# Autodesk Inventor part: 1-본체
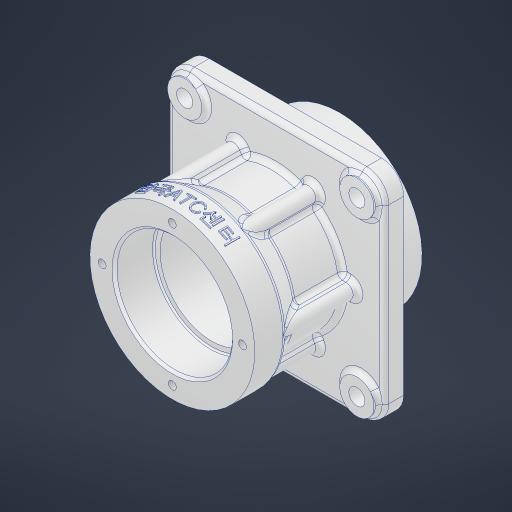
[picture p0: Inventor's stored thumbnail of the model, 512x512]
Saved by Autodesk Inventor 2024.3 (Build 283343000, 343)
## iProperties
Created: 2025-08
Part Number: 1-본체
Material: 알루미늄 6061
Document SubType Name: Modeling
Designer: user
Density: 2.7 g/cm^3
Appearance: 알루미늄 - 평지
Mass: 400.714 g
Surface Area: 396.891 cm^2
Volume: 148.413 cm^3
Author: user
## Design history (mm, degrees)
sketch "스케치1"
  geometry: L1 (0, 0)-(68, 0); L2 (0, 33.5)-(12, 33.5); L3 (12, 33.5)-(22, 27.5); L4 (0, 33.5)-(0, 0); L5 (22, 27.5)-(55, 27.5); L6 (55, 33.5)-(68, 33.5); L7 (68, 33.5)-(68, 0); L8 (55, 33.5)-(55, 27.5)
  constraints: 16 end point, 3 horizontal, 2 vertical, 1 parallel, 1 perpendicular
  dimensions: "d0" = 68 distance of L1.start L1.end; "d1" = 67 diameter of L2 L1; "d2" = 12 distance of L2.start L2.end; "d4" = 55 diameter of L5 L1; "d5" = 67 diameter of L6 L1; "d6" = 22 horizontal distance of L3.end L2.start; "d7" = 13 distance of L6.start L6.end
revolve "회전1" sketch "스케치1" stored, may be unused: angle "d8" = 90 deg
sketch "스케치2"
  geometry: C1 r 27.5 at (0, 0) reference; C2 r 33.5 at (0, 0) reference; C3 r 38.5 at (0, 0)
  constraints: 1 centre point, 1 coincident
  dimensions: "d9" = 77 diameter of C3
extrude "돌출1" join sketch "스케치2" distance "d10" = 5; taper "d11" = 0 deg
sketch "스케치3"
  geometry: L1 (-44, 44)-(44, 44); L2 (44, 44)-(44, -44); L3 (44, -44)-(-44, -44); L4 (-44, -44)-(-44, 44); C1 r 38.5 at (0, 0) reference; C2 r 27.5 at (0, 0) reference; 2 further points
  constraints: 8 end point, 2 midpoint, 2 parallel, 1 horizontal, 1 horizontal alignment, 1 perpendicular, 1 vertical alignment
  dimensions: "d12" = 88 distance of L2.end L3.end; "d13" = 88 distance of L1.end L2.end
extrude "돌출2" join sketch "스케치3" distance "d14" = 8; taper "d15" = 0 deg
fillet "모깎기1" dims "d16" = 9
sketch "스케치4"
  geometry: C1 r 7 at (-35, 35); C2 r 7 at (35, 35); C3 r 7 at (35, -35); C4 r 7 at (-35, -35); A1 r 9 centre (-35, -35) between (-44, -35) and (-35, -44) reference; A2 r 9 centre (35, -35) between (35, -44) and (44, -35) reference; A3 r 9 centre (35, 35) between (44, 35) and (35, 44) reference; A4 r 9 centre (-35, 35) between (-35, 44) and (-44, 35) reference
  constraints: 4 centre point, 4 coincident
  dimensions: "d17" = 14 diameter of C1; "d18" = 14 diameter of C2; "d19" = 14 diameter of C3; "d20" = 14 diameter of C4
extrude "돌출3" join sketch "스케치4" distance "d21" = 2; taper "d22" = 0 deg
fillet "모깎기2" dims "d23" = 2
sketch "스케치5"
  geometry: A1 r 7 centre (35, 35) between (40.444, 30.6) and (30.6, 40.444) reference; A2 r 7 centre (-35, 35) between (-40.444, 30.6) and (-30.6, 40.444) reference; A3 r 7 centre (35, -35) between (30.6, -40.444) and (40.444, -30.6) reference; A4 r 7 centre (-35, -35) between (-30.6, -40.444) and (-40.444, -30.6) reference; 5 further points
  constraints: 4 coincident
hole "구멍1" sketch "스케치5" at (35, 35), (-35, 35), (35, -35), (-35, -35) diameter "d24" = 6.6; stored, may be unused: countersink angle "d28" = 90 deg, drill point angle "d30" = 118 deg; dims "d25" = 6, "d26" = 4, "d27" = 2, "d29" = 8
fillet "모깎기6" dims "d78" = 2
sketch "스케치6"
  geometry: L1 (0, 0)-(33.5, 0); L2 (30.5, 3)-(27.336, 3); L3 (30.5, -3)-(27.336, -3); A1 r 27.5 centre (0, 0) between (27.336, 3) and (27.336, -3) reference; A2 r 3 centre (30.5, 0) between (27.5, 0) and (30.5, -3); A3 r 3 centre (30.5, 0) between (30.5, 3) and (27.5, 0); A4 r 3 centre (30.5, 0) between (30.5, -3) and (30.5, 3)
  constraints: 11 point on circle, 6 end point, 4 tangent, 3 centre point, 2 horizontal, 1 horizontal alignment, 1 parallel, 1 point on line, 1 other
  dimensions: "d31" = 6 diameter of A2
extrude "돌출4" join sketch "스케치6" stored distance "d32" = 2; taper "d33" = 0 deg
sketch "스케치7"
  geometry: C1 r 33.5 at (0, 0) reference; C2 r 23.5 at (0, 0)
  constraints: 1 centre point, 1 coincident
  dimensions: "d37" = 47 diameter of C2
extrude "돌출5" cut sketch "스케치7" distance "d38" = 16; taper "d39" = 0 deg
sketch "스케치8"
  geometry: C1 r 23.5 at (0, 0) reference; C2 r 21 at (0, 0)
  constraints: 1 centre point, 1 coincident
  dimensions: "d40" = 42 diameter of C2
extrude "돌출6" cut sketch "스케치8" extent not by distance; stored distance "d41" = 0; taper "d42" = 0 deg
sketch "스케치9"
  geometry: C1 r 21 at (0, 0) reference; C2 r 33.5 at (0, 0) reference; C3 r 23.5 at (0, 0)
  constraints: 1 centre point, 1 coincident
  dimensions: "d43" = 47 diameter of C3
extrude "돌출7" cut sketch "스케치9" distance "d44" = 16; taper "d45" = 0 deg
chamfer "모따기1" distance "d46" = 1; stored, may be unused: second distance "d47" = 2, angle "d48" = 45 deg
fillet "모깎기3" dims "d49" = 0.6
sketch "스케치10"
  geometry: L1 (0, 0)-(0, 28.5); C1 r 24.5 at (0, 0) reference; 1 further point
  constraints: 2 end point, 1 coincident, 1 vertical
  dimensions: "d51" = 28.5 distance of L1.start L1.end
hole "구멍2" sketch "스케치10" at (0, 28.5) diameter "d52" = 3.242; stored, may be unused: countersink angle "d56" = 90 deg, drill point angle "d58" = 118 deg; dims "d53" = 8, "d54" = 4, "d55" = 2, "d57" = 10
sketch "스케치11"
  geometry: L1 (0, 0)-(0, 28.5); C1 r 24.5 at (0, 0) reference; 1 further point
  constraints: 2 end point, 1 coincident, 1 vertical
  dimensions: "d62" = 28.5 distance of L1.start L1.end
hole "구멍3" sketch "스케치11" at (0, 28.5) diameter "d63" = 3.242; stored, may be unused: countersink angle "d67" = 90 deg, drill point angle "d69" = 118 deg; dims "d64" = 8, "d65" = 4, "d66" = 2, "d68" = 10
chamfer "모따기2" distance "d73" = 1; stored, may be unused: second distance "d74" = 2, angle "d75" = 45 deg
fillet "모깎기5" dims "d77" = 2
fillet "모깎기7" dims "d79" = 2
fillet "모깎기8" dims "d80" = 2
fillet "모깎기9" dims "d81" = 2
node "작업 평면1"
sketch "스케치12" dims "d0" = 68, "d1" = 67, "d2" = 12, "d4" = 55, "d5" = 67, "d6" = 22, "d7" = 13
  geometry: L1 (6, 33.5)-(-5.446, 33.5) reference; L2 (6, 33.5)-(6, -33.5) reference; L3 (-5.446, 33.5)-(-5.446, 16.75) reference; L4 (-5.446, 16.75)-(-5.446, 33.5) reference; L5 (-5.446, -16.75)-(-5.446, 16.75) reference; L6 (-5.446, -33.5)-(-5.446, -16.75) reference; L7 (-5.446, -16.75)-(-5.446, -33.5) reference; L8 (-5.446, 16.75)-(-5.446, -16.75) reference; L9 (6, 33.5)-(6, -33.5) reference; 2 further points
  constraints: 1 horizontal alignment, 1 other
  dimensions: "d82" = 6 horizontal distance of L1.start point (0, 0)
feature "엠보싱1" sketch "스케치12" dims "d0" = 68, "d1" = 67, "d2" = 12, "d4" = 55, "d5" = 67, "d6" = 22, "d7" = 13, "d83" = 0.5, "d84" = 0
feature "ƌ耀Ǝ耀Ɛ耀ƒ耀Ɣ耀Ɩ耀Ƙ耀ƚ耀" dims "d0" = 68, "d1" = 67, "d2" = 12, "d4" = 55, "d5" = 67, "d6" = 22, "d7" = 13, "d8" = 90 deg, "d9" = 77, "d10" = 5, "d11" = 0, "d12" = 88, "d13" = 88, "d14" = 8, "d15" = 0, "d16" = 9, "d17" = 14, "d18" = 14, "d19" = 14, "d20" = 14, "d21" = 2, "d22" = 0, "d23" = 2, "d24" = 6.6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
feature "Ϲ耀ϻ耀Ͻ耀Ͽ耀Ё耀Ѓ耀Ѕ耀Ї耀" dims "d0" = 68, "d1" = 67, "d2" = 12, "d4" = 55, "d5" = 67, "d6" = 22, "d7" = 13, "d8" = 90 deg, "d9" = 77, "d10" = 5, "d11" = 0, "d12" = 88, "d13" = 88, "d14" = 8, "d15" = 0, "d16" = 9, "d17" = 14, "d18" = 14, "d19" = 14, "d20" = 14, "d21" = 2, "d22" = 0, "d23" = 2, "d24" = 6.6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
node "솔리드1"
pattern_circular "원형 패턴1" dims angle "d35" = 360 deg
pattern_circular "원형 패턴2" dims angle "d60" = 360 deg
pattern_circular "원형 패턴3" dims angle "d71" = 360 deg
node "투영된 루프1"
feature "A9D066F2-1C7D-4E18-AEED-F7BC21143FA4" dims "d24" = 6.6, "d25" = 6, "d26" = 4, "d27" = 2, "d28" = 90 deg, "d29" = 8, "d30" = 118 deg
